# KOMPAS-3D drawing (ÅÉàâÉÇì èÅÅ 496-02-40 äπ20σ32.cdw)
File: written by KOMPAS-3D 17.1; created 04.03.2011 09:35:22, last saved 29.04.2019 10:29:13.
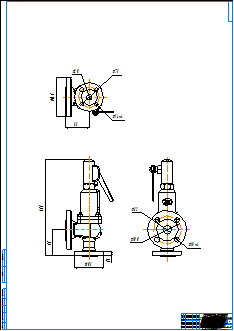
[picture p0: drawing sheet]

Sheet 1: A0, portrait

Title block, sheet 1: name: ПРЕГРАН КПП 496-02-40 / Ду20х32; material: Внимание! Данный продукт является объектом авторского права ООО «Торговый Дом АДЛ». / Запрещается изменение, копирование, распространение / (в том числе путем копирования на другие сайты и ресурсы в Интернете) / или любое иное использование информации и объектов без предварительного / согласия правообладателя (ООО «Торговый Дом АДЛ»).; scale: 1:1; sheets: 1; organisation: ООО "Торговый дом АДЛ"; sheet format: A0; stored path: C:\Users\tra\Desktop\2д чертежи\Предохранительные клапаны ПРЕГРАН\ПРЕГРАН 496\ПРЕГРАН КПП 496-02-40\KOMPAS 2D\ПРЕГРАН КПП 496-02-40 Ду20х32.cdw

Views: Спереди 1, Проекционный вид 2, Проекционный вид 3
Dimensions and other numbers on the sheet: 105; 95; 350; 16; 85; 75; 14; 140; 20; 100; 18; 32; 1:1; 1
